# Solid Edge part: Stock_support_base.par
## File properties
Title: Stock Support Base
Author: Deepak Maini
Template: Normal.par
Last saved by: Robert a Rhodes jr
Revision: 17
Application: Solid Edge
Material: aluminum
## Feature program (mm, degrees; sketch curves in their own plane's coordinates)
sketch for "unnamed RevolvedProtrusion 1" plane through (0, 0, 0) normal (0, -1, 0) x-axis (1, 0, 0)
  line (0, 29.2468) -> (71.7103, 29.2468)
  line (71.7103, 29.2468) -> (71.7103, 19.7218)
  line (71.7103, 19.7218) -> (165.1, -256.5032)
  line (165.1, -256.5032) -> (215.9, -256.5032)
  line (215.9, -256.5032) -> (215.9, -281.9032)
  line (215.9, -281.9032) -> (156.9298, -281.9032)
  line (156.9298, -281.9032) -> (85.052, -69.3053)
  arc centre (73.021, -73.3729) radius 12.7 from (60.325, -73.0538) to (85.052, -69.3053) cw
  line (60.325, -73.0538) -> (57.15, -199.3532)
  line (57.15, -199.3532) -> (0, -199.3532)
  line (0, 29.2468) -> (0, -199.3532)
revolve "unnamed RevolvedProtrusion 1" add full turn 360 deg
sketch for "unnamed Hole 1" plane through (0, 0, 29.2468) normal (0, 0, 1) x-axis (1, 0, 0)
  hole centre (0, 0) bore radius 38.1
hole "unnamed Hole 1" through
sketch for "unnamed Protrusion 1" plane through (0, 0, -256.5032) normal (0, 0, 1) x-axis (0, 1, 0)
  arc centre (0, -119.2664) radius 41.0756 from (-18.7686, -155.8034) to (18.7686, -155.8034) ccw
  line (-18.7686, -197.1314) -> (-18.7686, -155.8034)
  arc centre (0, -197.1314) radius 18.7686 from (18.7686, -197.1314) to (-18.7686, -197.1314) cw
  line (18.7686, -197.1314) -> (18.7686, -155.8034)
extrude "unnamed Protrusion 1" add finite 12.7 along +normal
sketch for "unnamed Hole 2" plane through (187.8036, 0, -243.8032) normal (0, 0, 1) x-axis (1, 0, 0)
hole "unnamed Hole 2" through
fillet "unnamed Round 1"
pattern "unnamed Pattern 1" of "unnamed Protrusion 1", "unnamed Hole 2", "unnamed Round 1"
pattern "unnamed Pattern 2"
sketch for "unnamed Protrusion 2" plane through (0, -134.62, 0) normal (0, -1, 0) x-axis (1, 0, 0)
  circle centre (0, -2.5032) radius 19.05
extrude "unnamed Protrusion 2" add
adv blend "unnamed AdvBlend 1"
sketch for "unnamed Protrusion 3" plane through (0, -134.62, -2.5032) normal (0, -1, 0) x-axis (1, 0, 0)
  circle centre (0, -3.81) radius 22.225
extrude "unnamed Protrusion 3" add finite 9.525 along +normal
mirror "unnamed Mirror 1" of "unnamed Protrusion 3", "unnamed AdvBlend 1", "unnamed Protrusion 2" about plane through (0, 0, 0) normal (0, -1, 0)
extrude "unnamed Protrusion 4" add
adv blend "unnamed AdvBlend 2"
extrude "unnamed Protrusion 5" add finite 9.525
sketch for "unnamed Protrusion 6" plane through (104.775, 0, 0) normal (1, 0, 0) x-axis (0, 1, 0)
  circle centre (0, -167.6032) radius 19.05
extrude "unnamed Protrusion 6" add finite 41.275 along +normal
sketch for "unnamed Hole 3" plane through (146.05, 0, -167.6032) normal (1, 0, 0) x-axis (0, 1, 0)
  hole centre (0, 0) bore radius 7.9375
hole "unnamed Hole 3" through
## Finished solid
Body 1: solid body, 54 faces, 95 edges, 41 vertices.
  Faces by surface: plane 26, cylinder 19, torus 4, cone 3, blend 2
  Edges by curve: circle 57, intersection 20, line 18
Bounding box of the edges (mm; curved faces can reach further): 431.800 x 431.800 x 311.150, from (-215.9, -215.9, -281.9032) to (215.9, 215.9, 29.2468).
Cylindrical faces by radius (mm): R7.9375 x1, R11.1125 x3, R15.875 x3, R18.7686 x3, R19.05 x4, R22.225 x2, R38.1 x1, R71.7103 x1, R215.9 x1
Conical faces (half-angle, radius in mm at the cone's reference point): 1.44 deg R60.325 x1, 18.68 deg R71.7103 x1, 18.68 deg R156.9298 x1
Toroidal faces (ring radius, tube radius in mm): R73.021 r12.7 x1, R163.0843 r3.175 x3
Planar faces by outward normal: +x 1, +y 4, +z 10, -x 1, -y 4, -z 2, oblique 4
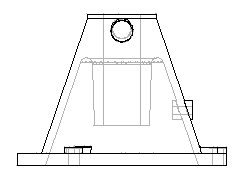
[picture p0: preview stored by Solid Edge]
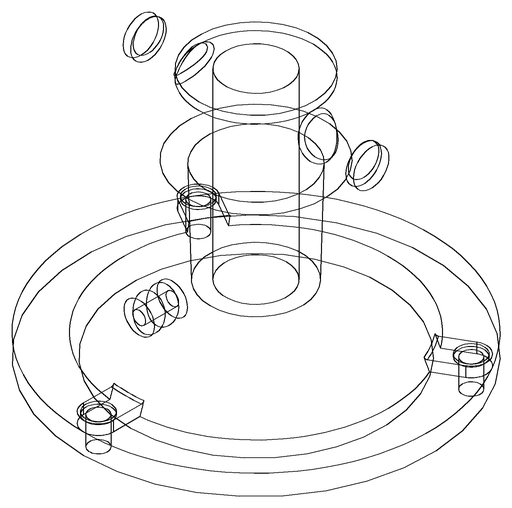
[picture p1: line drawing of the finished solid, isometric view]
